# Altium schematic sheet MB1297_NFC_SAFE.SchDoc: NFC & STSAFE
size A4; Date: Not used; ApprovedBy: Not used; CheckedBy: Not used; Author: Not used; CompanyName: STMicroelectronics; DrawnBy: Not used; Engineer: Not used; Organization: Not used; Address1: Not used; Address2: Not used; Address3: Not used; Address4: Not used; DocumentNumber: Not used; Revision: Not used; SheetNumber: 8; SheetTotal: 12
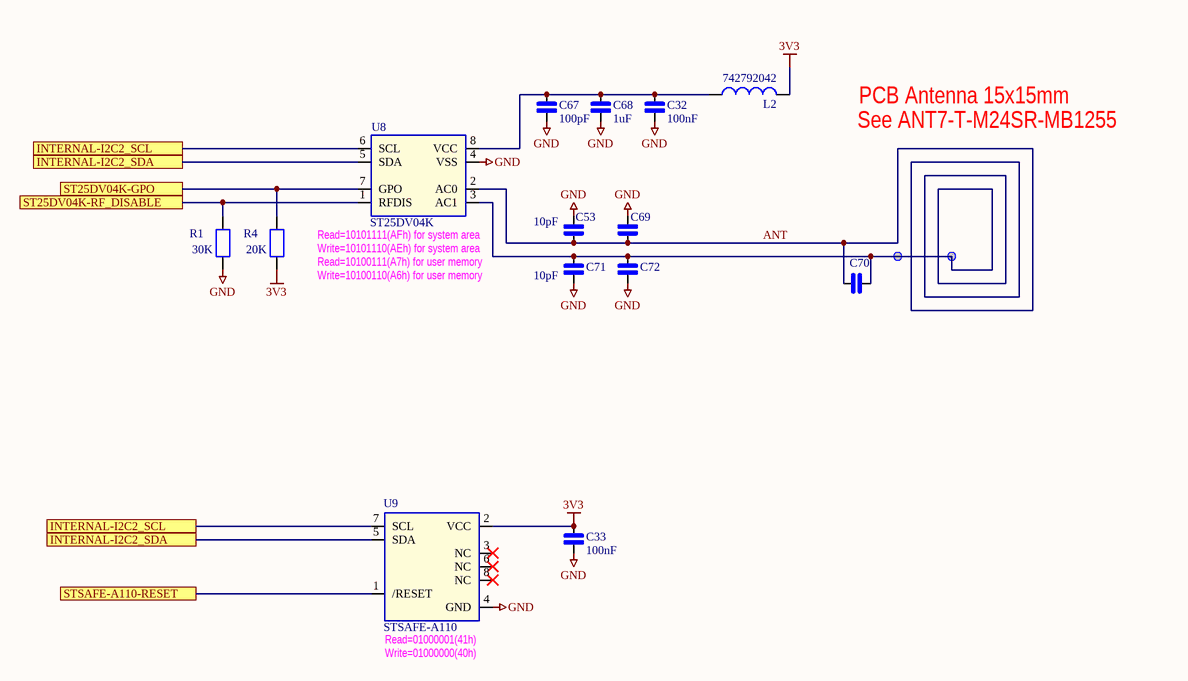
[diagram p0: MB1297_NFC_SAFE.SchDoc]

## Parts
C32  100nF  [0402]
C33  100nF  [0402]
C53  10pF  [0402]
C67  100pF  [0402]
C68  1uF  [0402]
C69  (no value)  [0402]
C70  (no value)  [0402]
C71  10pF  [0402]
C72  (no value)  [0402]
L2  742792042  [0603L]
R1  30K  [0402]
R4  20K  [0402]
U8  ST25DV04K  [SOP8]
U9  STSAFE-A110  [SOP8]

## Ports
INTERNAL-I2C2_SCL, INTERNAL-I2C2_SDA, ST25DV04K-GPO, ST25DV04K-RF_DISABLE, STSAFE-A110-RESET

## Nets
3V3: C33.1 L2.2 R4.1 U9.2(VCC)
GND: C32.2 C33.2 C53.2 C67.2 C68.2 C69.2 C71.2 C72.2 R1.1 U8.4(VSS) U9.4(GND)
ANT: C53.1 C69.1 C70.1 C70.2 C71.1 C72.1 U8.2(AC0) U8.3(AC1)
INTERNAL-I2C2_SCL: U8.6(SCL) U9.7(SCL) ; port INTERNAL-I2C2_SCL
INTERNAL-I2C2_SDA: U8.5(SDA) U9.5(SDA) ; port INTERNAL-I2C2_SDA
ST25DV04K-GPO: R4.2 U8.7(GPO) ; port ST25DV04K-GPO
ST25DV04K-RF_DISABLE: R1.2 U8.1(RFDIS) ; port ST25DV04K-RF_DISABLE
STSAFE-A110-RESET: U9.1(/RESET) ; port STSAFE-A110-RESET
NetC32_1: C32.1 C67.1 C68.1 L2.1 U8.8(VCC)

Not connected (* = marked no-connect by the designer): U9 3(NC)* 6(NC)* 8(NC)*

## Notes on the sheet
- PCB Antenna 15x15mm
- See ANT7-T-M24SR-MB1255
- Read=10101111(AFh) for system area
- Write=10101110(AEh) for system area
- Read=10100111(A7h) for user memory
- Write=10100110(A6h) for user memory
- (near U9) Read=01000001(41h)
- (near U9) Write=01000000(40h)

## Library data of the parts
C32 C33 C53 C67-C72 = CAP_NPOL: Capacitor_not polarized
L2 = Inductor: Value: 100uH
R1 R4 = RES: Resistor
U8 = M24SR64-Y: ST25DV04K 64K_EEPROM NFC/RFID
U9 = STSAFE-A100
